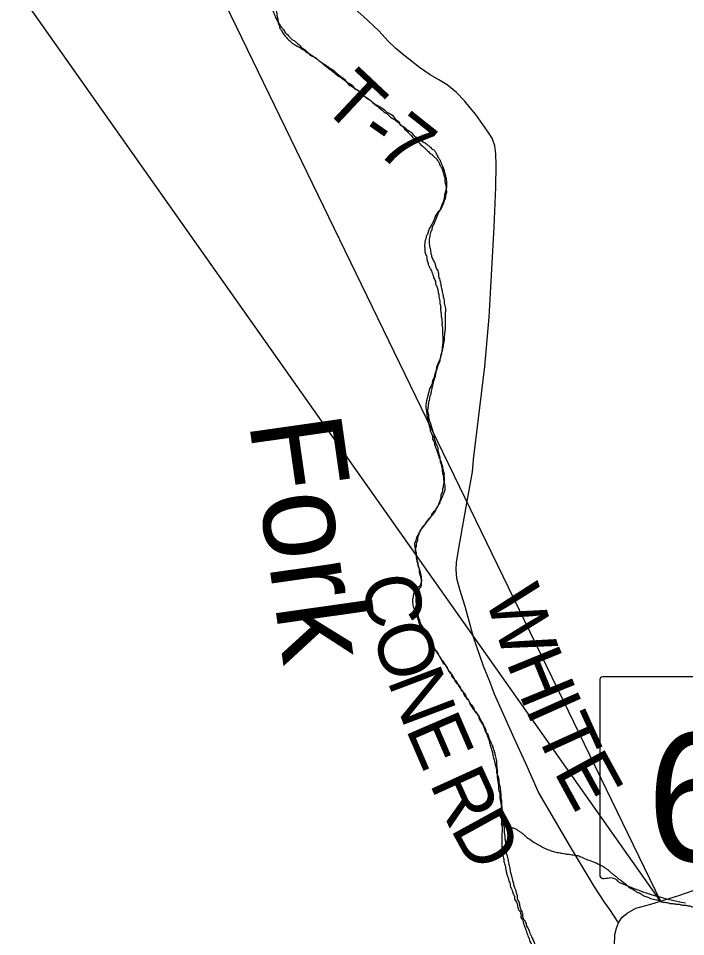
# Model space of a CAD drawing. Extents: x -13.7 to 34, y 0 to 32.3.
# Drawn here: x 26.173 to 26.859, y 17.062 to 18.005 of the extents above; entities that cross this region are included whole.
import ezdxf

# ---------------------------------------------------------------- set-up
doc = ezdxf.new("R2010")
doc.units = 0
for name, color, linetype in [('GM_X_Minor_River', 7, 'Continuous'), ('GM_X_Minor_River_Text', 7, 'Continuous'), ('GM_X_State_Route', 7, 'Continuous'), ('GM_X_State_Shield', 7, 'Continuous'), ('GM_X_Township_Road', 7, 'Continuous'), ('GM_X_Township_Road_Text', 7, 'Continuous'), ('SH_Text', 7, 'Continuous')]:
    doc.layers.add(name, color=color, linetype=linetype)

msp = doc.modelspace()

# ---------------------------------------------------------------- linework, layer by layer
at = {"layer": 'GM_X_Minor_River'}
for points in [[(26.37946, 18.13129), (26.38076, 18.13171), (26.38145, 18.1294), (26.38367, 18.12781), (26.38511, 18.12548), (26.3862, 18.12393), (26.38691, 18.12239), (26.38834, 18.11968), (26.39049, 18.11581), (26.39082, 18.11428), (26.393, 18.11154), (26.39548, 18.10615), (26.39689, 18.10268), (26.39832, 18.09997), (26.39825, 18.09807), (26.40041, 18.09458), (26.40287, 18.08842), (26.40317, 18.08613), (26.40495, 18.08265), (26.40844, 18.07342), (26.41095, 18.06878), (26.41128, 18.06725), (26.41272, 18.06492), (26.41451, 18.06182), (26.41593, 18.05873), (26.41737, 18.0564), (26.4188, 18.0537), (26.42129, 18.04868), (26.42238, 18.04712), (26.42308, 18.04558), (26.42417, 18.04402), (26.42523, 18.04171), (26.42592, 18.0394), (26.42767, 18.03517), (26.42904, 18.03056), (26.42936, 18.02865), (26.43041, 18.02596), (26.43181, 18.02249), (26.43176, 18.02097), (26.43247, 18.01943), (26.43351, 18.01636), (26.4349, 18.01251), (26.43595, 18.00982), (26.437, 18.00712), (26.43806, 18.00481), (26.43913, 18.00287), (26.43984, 18.00133), (26.44052, 17.99903), (26.44123, 17.99748), (26.44156, 17.99595), (26.44227, 17.99441), (26.44336, 17.99285), (26.44588, 17.98897), (26.4488, 17.98545), (26.45064, 17.98349), (26.45248, 17.98191), (26.45395, 17.98034), (26.45581, 17.97914), (26.45767, 17.97794), (26.46214, 17.97551), (26.46437, 17.97392), (26.4666, 17.97271), (26.46882, 17.97073), (26.47031, 17.96992), (26.4796, 17.96392), (26.4885, 17.95754), (26.49036, 17.95634), (26.4922, 17.95476), (26.49444, 17.95355), (26.50036, 17.94879), (26.5022, 17.94721), (26.50554, 17.94482), (26.50886, 17.94205), (26.51181, 17.93929), (26.51737, 17.93531), (26.51808, 17.93376), (26.52365, 17.93016), (26.52434, 17.92786), (26.52694, 17.92625), (26.53326, 17.92224), (26.53549, 17.92065), (26.5377, 17.91868), (26.53918, 17.91749), (26.54141, 17.91627), (26.54922, 17.91146), (26.55217, 17.9087), (26.55591, 17.90706), (26.56141, 17.90117), (26.56472, 17.89802), (26.56505, 17.89649), (26.56765, 17.89451), (26.5702, 17.89138), (26.57204, 17.8898), (26.57498, 17.88667), (26.5816, 17.88037), (26.58345, 17.87879), (26.58603, 17.87642)], [(26.43245, 18.03045), (26.43384, 18.02661), (26.43491, 18.02429), (26.43524, 18.02276), (26.43594, 18.02121), (26.43765, 18.01546), (26.43795, 18.01317), (26.43861, 18.01011), (26.43889, 18.00706), (26.43957, 18.00476), (26.43988, 18.00247), (26.44093, 17.99977), (26.44201, 17.99822), (26.4431, 17.99666), (26.44601, 17.99277), (26.44708, 17.99083), (26.44856, 17.98964), (26.4526, 17.98533), (26.45481, 17.98335), (26.4563, 17.98254), (26.45926, 17.98017), (26.4611, 17.97859), (26.46258, 17.9774), (26.46367, 17.97584), (26.46515, 17.97465), (26.46997, 17.97107), (26.47327, 17.96754), (26.47476, 17.96674), (26.47737, 17.96551), (26.48625, 17.95838), (26.48995, 17.95559), (26.49439, 17.95203), (26.49846, 17.94885), (26.50402, 17.94487), (26.50588, 17.94367), (26.50772, 17.94209), (26.5092, 17.9409), (26.51068, 17.93971), (26.51362, 17.93657), (26.51549, 17.93575), (26.51883, 17.93336), (26.52032, 17.93255), (26.52254, 17.93096), (26.5255, 17.92858), (26.53288, 17.92226), (26.53437, 17.92145), (26.53695, 17.91908), (26.54028, 17.91631), (26.54361, 17.91392), (26.55026, 17.90838), (26.55175, 17.90757), (26.55395, 17.90522), (26.55729, 17.90283), (26.56026, 17.90083), (26.56174, 17.89964), (26.56397, 17.89805), (26.5684, 17.89448), (26.5699, 17.89367), (26.57136, 17.89211), (26.57395, 17.89012), (26.57581, 17.88892), (26.57729, 17.88773), (26.57874, 17.88578), (26.58208, 17.88339), (26.58358, 17.88296), (26.58543, 17.88138), (26.5869, 17.87981), (26.58914, 17.8786), (26.59099, 17.8774), (26.59322, 17.8758), (26.59543, 17.87383), (26.59691, 17.87264), (26.59838, 17.87107), (26.59987, 17.87026), (26.60205, 17.86753), (26.60347, 17.86444), (26.60455, 17.86251), (26.60635, 17.85979), (26.6074, 17.85709), (26.60845, 17.8544), (26.60916, 17.85286), (26.60986, 17.85093), (26.61056, 17.84939), (26.61088, 17.84748), (26.61155, 17.8448), (26.61256, 17.84097), (26.61284, 17.83792), (26.61313, 17.83525), (26.61304, 17.83259), (26.61259, 17.83033), (26.61171, 17.82656), (26.61085, 17.82354), (26.61077, 17.82127), (26.61034, 17.81976), (26.60991, 17.81825), (26.60825, 17.81375), (26.60698, 17.80999)], [(26.58603, 17.87642), (26.58749, 17.87485), (26.59118, 17.87169), (26.59265, 17.87012), (26.5945, 17.86854), (26.59596, 17.86697), (26.59782, 17.86577), (26.60002, 17.86342), (26.6026, 17.86105), (26.60369, 17.8595), (26.60551, 17.85716), (26.60619, 17.85486), (26.60799, 17.85176), (26.60937, 17.84791), (26.6104, 17.84446), (26.61139, 17.83986), (26.61131, 17.83759), (26.61233, 17.83413), (26.6126, 17.83071), (26.6129, 17.82804), (26.61284, 17.82652), (26.6124, 17.82463), (26.61192, 17.82161), (26.61148, 17.81972), (26.61067, 17.81823), (26.61024, 17.81672), (26.60942, 17.81485), (26.60859, 17.8126), (26.60696, 17.80923), (26.6042, 17.80629), (26.60016, 17.79882), (26.59892, 17.79582), (26.59569, 17.78985), (26.59403, 17.78573), (26.59359, 17.78384), (26.5924, 17.78236), (26.59195, 17.78009), (26.59109, 17.77708), (26.59061, 17.77406), (26.59051, 17.77102), (26.59076, 17.76722), (26.59071, 17.7657), (26.59139, 17.7634), (26.59277, 17.75917), (26.59272, 17.75765), (26.59342, 17.75573), (26.5941, 17.75343), (26.59514, 17.75035), (26.59585, 17.74881), (26.59693, 17.74725), (26.59798, 17.74456), (26.59903, 17.74186), (26.60006, 17.73841), (26.60183, 17.73455), (26.60178, 17.73303), (26.60284, 17.73072), (26.60386, 17.72727), (26.60485, 17.72267), (26.60517, 17.72076), (26.60546, 17.71809), (26.60613, 17.71541), (26.60608, 17.71389), (26.60673, 17.71083), (26.60699, 17.70702), (26.60694, 17.70551), (26.60726, 17.7036), (26.60751, 17.69979), (26.60784, 17.69826), (26.60815, 17.69635), (26.60841, 17.69254), (26.60836, 17.69102), (26.60867, 17.68911), (26.60894, 17.68568), (26.60883, 17.68227), (26.60909, 17.67884), (26.6087, 17.66707), (26.6082, 17.66329), (26.60772, 17.66027), (26.60729, 17.65876), (26.60644, 17.65613), (26.60598, 17.65348), (26.60553, 17.6516), (26.60472, 17.65011), (26.60388, 17.64747), (26.60221, 17.64297), (26.60177, 17.64108), (26.60083, 17.63579), (26.60001, 17.63392), (26.59917, 17.63129), (26.59869, 17.62827), (26.59783, 17.62526), (26.59736, 17.62261), (26.59648, 17.61884), (26.59562, 17.61583), (26.59515, 17.61318), (26.59424, 17.60866), (26.59417, 17.60638)], [(26.60698, 17.80999), (26.60535, 17.80663), (26.60373, 17.80364), (26.60247, 17.79988), (26.60125, 17.79726), (26.60041, 17.79501), (26.5992, 17.79277), (26.59838, 17.7909), (26.59751, 17.78751), (26.59668, 17.78564), (26.59626, 17.78413), (26.59579, 17.78149), (26.59531, 17.77846), (26.59522, 17.77581), (26.5955, 17.77276), (26.59579, 17.77009), (26.59647, 17.76779), (26.59675, 17.76474), (26.59742, 17.76206), (26.59881, 17.75821), (26.59988, 17.7559), (26.60095, 17.75396), (26.60161, 17.7509), (26.60338, 17.74704), (26.60475, 17.74243), (26.60467, 17.74016), (26.60573, 17.73784), (26.60639, 17.73478), (26.60707, 17.73248), (26.60738, 17.73019), (26.60838, 17.72598), (26.6087, 17.72445), (26.60937, 17.72176), (26.60968, 17.71947), (26.61036, 17.71717), (26.61067, 17.71488), (26.61093, 17.71145), (26.6116, 17.70877), (26.61189, 17.7061), (26.61179, 17.70307), (26.61172, 17.70079), (26.61109, 17.68181), (26.61061, 17.67879), (26.61047, 17.67461), (26.60999, 17.67159), (26.60952, 17.66895), (26.60904, 17.66592), (26.60818, 17.66291), (26.60733, 17.6599), (26.60644, 17.65613), (26.60601, 17.65462), (26.60226, 17.64449), (26.60221, 17.64297), (26.60139, 17.6411), (26.60052, 17.63771), (26.60009, 17.6362), (26.59845, 17.63245), (26.5984, 17.63094), (26.59675, 17.62719), (26.59423, 17.61968), (26.59334, 17.6159), (26.59291, 17.6144), (26.59247, 17.61251), (26.59217, 17.60341), (26.5925, 17.60187), (26.59273, 17.59731), (26.5934, 17.59463), (26.59406, 17.59156), (26.5947, 17.58812), (26.59607, 17.58352), (26.59638, 17.58161), (26.59743, 17.57891), (26.59882, 17.57507), (26.59876, 17.57317), (26.59983, 17.57123), (26.60051, 17.56855), (26.60153, 17.5651), (26.60258, 17.5624), (26.60397, 17.55856), (26.60464, 17.55588), (26.60712, 17.55047), (26.60779, 17.54779), (26.60884, 17.5451), (26.60879, 17.54358), (26.60947, 17.54128), (26.6098, 17.53975), (26.61051, 17.5382), (26.61043, 17.53593), (26.61071, 17.53288), (26.61061, 17.52984), (26.6109, 17.52717), (26.61063, 17.51882), (26.60982, 17.51733), (26.60855, 17.51357), (26.6061, 17.50833), (26.60567, 17.50683), (26.60449, 17.50535)], [(26.59417, 17.60638), (26.59371, 17.60411), (26.59364, 17.60184), (26.59394, 17.59955), (26.59464, 17.59762), (26.59458, 17.59611), (26.59663, 17.5892), (26.59696, 17.58767), (26.59765, 17.58537), (26.59868, 17.58229), (26.59935, 17.57961), (26.60004, 17.57731), (26.59999, 17.57579), (26.60169, 17.57003), (26.60202, 17.5685), (26.6031, 17.56657), (26.60441, 17.56044), (26.60544, 17.55699), (26.60611, 17.55431), (26.60639, 17.55126), (26.60704, 17.5482), (26.60839, 17.54283), (26.60868, 17.54016), (26.60932, 17.53672), (26.61001, 17.53442), (26.60995, 17.5329), (26.61026, 17.53061), (26.61018, 17.52834), (26.6097, 17.52531), (26.60924, 17.52267), (26.60881, 17.52116), (26.60876, 17.51964), (26.60792, 17.51739), (26.60705, 17.514), (26.607, 17.51248), (26.60615, 17.50985), (26.60489, 17.50609), (26.60408, 17.5046), (26.60327, 17.50311), (26.60205, 17.50049), (26.59411, 17.49011), (26.59251, 17.4875), (26.59052, 17.48491), (26.58934, 17.48343), (26.58736, 17.48122), (26.58416, 17.476), (26.58332, 17.47375), (26.58212, 17.47189), (26.58165, 17.46925), (26.58044, 17.46701), (26.58032, 17.46321), (26.5813, 17.45862), (26.58191, 17.45404), (26.58249, 17.4487), (26.5832, 17.44716), (26.58349, 17.44449), (26.58486, 17.43988), (26.58555, 17.43796), (26.58622, 17.43528), (26.58714, 17.42841), (26.58706, 17.42613), (26.58623, 17.42388), (26.5854, 17.422), (26.58347, 17.42093), (26.58192, 17.41984), (26.58111, 17.41835), (26.58027, 17.4161), (26.57909, 17.41462), (26.57904, 17.4131), (26.57861, 17.41159), (26.57856, 17.41007), (26.57813, 17.40857), (26.57805, 17.40629), (26.57834, 17.40362), (26.57865, 17.40133), (26.57934, 17.39941), (26.58076, 17.39632), (26.58146, 17.3944), (26.5814, 17.39288), (26.58247, 17.39057), (26.58421, 17.38595), (26.5849, 17.38365), (26.58706, 17.38015), (26.58993, 17.37512), (26.59024, 17.37321), (26.59244, 17.37086), (26.59424, 17.36776), (26.59533, 17.3662), (26.59677, 17.36387), (26.59784, 17.36194), (26.60001, 17.35845), (26.60218, 17.35534), (26.60399, 17.35262), (26.60543, 17.35029), (26.60652, 17.34873), (26.60867, 17.34486), (26.60937, 17.34332)], [(26.60449, 17.50535), (26.60248, 17.50199), (26.6005, 17.4994), (26.59772, 17.49569), (26.59648, 17.49269), (26.59334, 17.48976), (26.59135, 17.48678), (26.59054, 17.48529), (26.58858, 17.48346), (26.58697, 17.48085), (26.58534, 17.47748), (26.58411, 17.47448), (26.58325, 17.47147), (26.58318, 17.46957), (26.58276, 17.46807), (26.58191, 17.46544), (26.58186, 17.46392), (26.58097, 17.46015), (26.58123, 17.45634), (26.58254, 17.45022), (26.58281, 17.44679), (26.58385, 17.44372), (26.58418, 17.44218), (26.58486, 17.43988), (26.58481, 17.43836), (26.58544, 17.43454), (26.58647, 17.43109), (26.58711, 17.42765), (26.58704, 17.42537), (26.58612, 17.42084), (26.58453, 17.41861), (26.5837, 17.41636), (26.58289, 17.41487), (26.58207, 17.413), (26.58153, 17.40808), (26.58148, 17.40656), (26.58181, 17.40503), (26.58173, 17.40275), (26.58264, 17.39588), (26.58334, 17.39396), (26.58434, 17.38975), (26.58505, 17.3882), (26.58537, 17.38667), (26.58641, 17.3836), (26.58856, 17.37972), (26.5907, 17.37547), (26.59359, 17.3712), (26.59468, 17.36964), (26.59645, 17.36579), (26.59754, 17.36423), (26.59895, 17.36114), (26.60147, 17.35688), (26.60437, 17.35261), (26.60508, 17.35106), (26.60724, 17.34757), (26.6098, 17.34482), (26.61086, 17.34251), (26.61231, 17.34018), (26.61338, 17.33825), (26.61556, 17.33514), (26.61807, 17.33087), (26.6184, 17.32934), (26.62097, 17.3266), (26.62387, 17.3227), (26.62602, 17.31883), (26.62821, 17.3161), (26.63037, 17.31261), (26.6307, 17.31107), (26.63289, 17.30834), (26.63615, 17.30368), (26.63685, 17.30175), (26.63936, 17.29749), (26.64082, 17.29554), (26.64374, 17.29202), (26.647, 17.28736), (26.64841, 17.28427), (26.65021, 17.28117), (26.65161, 17.2777), (26.6534, 17.27422), (26.65335, 17.27271), (26.6548, 17.27076), (26.65656, 17.26652), (26.65796, 17.26305), (26.66008, 17.25843), (26.66078, 17.2565), (26.66146, 17.2542), (26.66216, 17.25228), (26.66282, 17.24922), (26.6635, 17.24691), (26.66417, 17.24423), (26.66445, 17.24118), (26.6644, 17.23966), (26.66468, 17.23661), (26.66526, 17.23127), (26.66519, 17.229), (26.6654, 17.22405), (26.66573, 17.22252)], [(26.60937, 17.34332), (26.61195, 17.34095), (26.61482, 17.33592), (26.61553, 17.33437), (26.61773, 17.33202), (26.62026, 17.32814), (26.62203, 17.32428), (26.62496, 17.32115), (26.62749, 17.31726), (26.62818, 17.31534), (26.63038, 17.31298), (26.63291, 17.3091), (26.63324, 17.30757), (26.63508, 17.30561), (26.63687, 17.30251), (26.63906, 17.29978), (26.64157, 17.29551), (26.6419, 17.29398), (26.64372, 17.29165), (26.64624, 17.28738), (26.64657, 17.28585), (26.64945, 17.28119), (26.65087, 17.27811), (26.65156, 17.27618), (26.65261, 17.27349), (26.6544, 17.27001), (26.65543, 17.26694), (26.65648, 17.26424), (26.65715, 17.26156), (26.65748, 17.26003), (26.65816, 17.25773), (26.65954, 17.2535), (26.66022, 17.2512), (26.66054, 17.24929), (26.66153, 17.2447), (26.66223, 17.24277), (26.66287, 17.23933), (26.6639, 17.23588), (26.66454, 17.23244), (26.66449, 17.23092), (26.66554, 17.22823), (26.66683, 17.22134), (26.66714, 17.21905), (26.66782, 17.21675), (26.66811, 17.21408), (26.66843, 17.21217), (26.66871, 17.20912), (26.66898, 17.20607), (26.66893, 17.20456), (26.66926, 17.20303), (26.66957, 17.20074), (26.66948, 17.19808), (26.66978, 17.19579), (26.66936, 17.18288), (26.66965, 17.18021), (26.66957, 17.17794), (26.66989, 17.17603), (26.67019, 17.17374), (26.66975, 17.16045), (26.67002, 17.15703), (26.66992, 17.15399), (26.67022, 17.1517), (26.6708, 17.14636), (26.67111, 17.14407), (26.67179, 17.14177), (26.67209, 17.13948), (26.67276, 17.1368), (26.67408, 17.13067), (26.67472, 17.12723), (26.67576, 17.12416), (26.67647, 17.12261), (26.67711, 17.11917), (26.67852, 17.11571), (26.67847, 17.11419), (26.67953, 17.11187), (26.68058, 17.10918), (26.68162, 17.1061), (26.68302, 17.10264), (26.68296, 17.10074), (26.6844, 17.09841), (26.6858, 17.09494), (26.68612, 17.09304), (26.68645, 17.0915), (26.68788, 17.0888), (26.68961, 17.0838), (26.68955, 17.0819), (26.69099, 17.07957), (26.69201, 17.07612), (26.69234, 17.07459), (26.69305, 17.07305), (26.6941, 17.07035), (26.69618, 17.0642), (26.69722, 17.06151), (26.69793, 17.05997), (26.6986, 17.05729), (26.70004, 17.05496), (26.70111, 17.05264)], [(26.66573, 17.22252), (26.66635, 17.21832), (26.66658, 17.21375), (26.6679, 17.20763), (26.66783, 17.20573), (26.66845, 17.20153), (26.66878, 17.2), (26.6694, 17.1958), (26.66973, 17.19427), (26.67035, 17.19007), (26.67029, 17.18817), (26.67057, 17.18512), (26.67118, 17.18054), (26.67112, 17.17902), (26.67179, 17.17634), (26.67243, 17.17252), (26.67232, 17.16911), (26.67293, 17.1649), (26.67289, 17.16339), (26.67353, 17.15995), (26.67344, 17.15729), (26.67443, 17.1527), (26.67462, 17.14699), (26.67532, 17.14507), (26.67597, 17.14201), (26.67695, 17.13704), (26.67726, 17.13513), (26.67793, 17.13244), (26.67858, 17.129), (26.6806, 17.12134), (26.68093, 17.11981), (26.68193, 17.11559), (26.68226, 17.11406), (26.68332, 17.11175), (26.68436, 17.10867), (26.68503, 17.10599), (26.68569, 17.10293), (26.68564, 17.10141), (26.6867, 17.09909), (26.68807, 17.09449), (26.68838, 17.09258), (26.68979, 17.08911), (26.69114, 17.08413), (26.69144, 17.08184), (26.69324, 17.07874), (26.695, 17.0745), (26.69533, 17.07297), (26.69677, 17.07064), (26.69817, 17.06718), (26.69922, 17.06448), (26.70064, 17.0614), (26.70171, 17.05946), (26.70241, 17.05754), (26.70347, 17.05522), (26.70414, 17.05254), (26.70593, 17.04944), (26.70698, 17.04675), (26.70951, 17.04286), (26.71089, 17.03864), (26.71417, 17.03435), (26.71594, 17.03049), (26.71883, 17.02622), (26.7206, 17.02236), (26.7224, 17.01926), (26.72418, 17.01578), (26.72413, 17.01426), (26.72594, 17.01154), (26.7277, 17.0073), (26.72765, 17.00578), (26.7291, 17.00384), (26.73052, 17.00075), (26.73155, 16.99768), (26.73297, 16.99459), (26.73292, 16.99307), (26.73399, 16.99113), (26.73502, 16.98768), (26.73566, 16.98424), (26.73668, 16.98041), (26.73803, 16.97542), (26.73798, 16.9739), (26.7386, 16.9697), (26.73924, 16.96626), (26.73954, 16.96359), (26.73938, 16.95904), (26.73893, 16.95677), (26.73885, 16.9545), (26.7384, 16.95223), (26.73815, 16.94464), (26.73769, 16.94238), (26.73725, 16.94049), (26.73696, 16.93176), (26.73725, 16.92909), (26.73787, 16.92489), (26.73922, 16.91953), (26.73953, 16.91762), (26.7402, 16.91493), (26.74126, 16.91262)], [(26.67114, 17.17897), (26.66917, 17.17719), (26.67143, 17.17673), (26.67368, 17.1759), (26.67594, 17.17545), (26.67819, 17.17461), (26.68158, 17.17374), (26.68383, 17.1729), (26.68643, 17.1713), (26.6894, 17.1693), (26.692, 17.16732), (26.69458, 17.16495), (26.69902, 17.16176), (26.7046, 17.15816), (26.70684, 17.15694), (26.70944, 17.15534), (26.71168, 17.15413), (26.71691, 17.15167), (26.71916, 17.15084), (26.72179, 17.14999), (26.72404, 17.14916), (26.72668, 17.14869), (26.7297, 17.14821), (26.73197, 17.14775), (26.73499, 17.14727), (26.73914, 17.14675), (26.74443, 17.14582), (26.74783, 17.14533), (26.75195, 17.14367), (26.75794, 17.14119), (26.76469, 17.13869), (26.77254, 17.13501), (26.77478, 17.13379), (26.77737, 17.13181), (26.77959, 17.13022), (26.78217, 17.12785), (26.78513, 17.12547), (26.78772, 17.12349), (26.79216, 17.11992), (26.7955, 17.11753), (26.79771, 17.11556), (26.80103, 17.11278), (26.80587, 17.10996), (26.80847, 17.10798), (26.81184, 17.10673), (26.81481, 17.10473), (26.81893, 17.10307), (26.82268, 17.10143), (26.8287, 17.10009), (26.83171, 17.09923), (26.83395, 17.09801), (26.83999, 17.09705), (26.84338, 17.09618), (26.84565, 17.09611), (26.84905, 17.09561), (26.85133, 17.09554), (26.85472, 17.09467), (26.85737, 17.09458), (26.85963, 17.09412), (26.86303, 17.09363), (26.86566, 17.09278), (26.8687, 17.09268), (26.87247, 17.09218), (26.87892, 17.09196), (26.88118, 17.09151), (26.8846, 17.0914), (26.88689, 17.0917), (26.88994, 17.09236), (26.89344, 17.0949), (26.89807, 17.09703), (26.90083, 17.09998), (26.90587, 17.10323), (26.91058, 17.10801), (26.91334, 17.11096), (26.91502, 17.11585), (26.92376, 17.12772), (26.92461, 17.13035), (26.92812, 17.13327), (26.93096, 17.13888), (26.93373, 17.14221), (26.93532, 17.14443), (26.93656, 17.14743), (26.94017, 17.15339), (26.9418, 17.15676), (26.94227, 17.1594), (26.94552, 17.16575), (26.94597, 17.16802), (26.94797, 17.17099), (26.94966, 17.17625), (26.95127, 17.17886), (26.95253, 17.18262), (26.95454, 17.18597), (26.95581, 17.19011), (26.95787, 17.19498), (26.96187, 17.20093), (26.96548, 17.20689), (26.96749, 17.21024)]]:
    msp.add_spline(points, degree=3, dxfattribs=at)
at = {"layer": 'GM_X_State_Route'}
msp.add_lwpolyline([(26.78576, 17.05253), (26.78594, 17.0644), (26.78764, 17.0708), (26.78979, 17.07635), (26.79308, 17.08189), (26.79869, 17.08634), (26.80744, 17.09133), (26.82288, 17.09536), (26.85177, 17.10446), (26.87331, 17.11184)], dxfattribs=at)
at = {"layer": 'GM_X_State_Shield'}
for p, q in [((26.87023, 17.32904), (26.77371, 17.32904)), ((26.77046, 17.3256), (26.77046, 17.12548))]:
    msp.add_line(p, q, dxfattribs=at)
for centre, major_axis, start_param, end_param in [((26.77424, 17.32602), (0.00382, 0), 1.712693, 3.28349), ((26.77427, 17.12504), (0.00385, 0), 3.00124, 4.508301), ((26.77486, 17.14551), (0.0294, 0), 4.665946, 4.897461), ((26.78087, 17.11393), (0.0106, 0), 0.519207, 1.627899), ((26.91469, 17.29373), (0.2524, 0), 4.195997, 4.488961)]:
    msp.add_ellipse(centre, major_axis=major_axis, ratio=0.8, start_param=start_param, end_param=end_param, dxfattribs=at)
at = {"layer": 'GM_X_Township_Road'}
msp.add_lwpolyline([(26.78979, 17.07635), (26.78076, 17.08989), (26.77523, 17.09769), (26.76517, 17.11329), (26.74054, 17.15433), (26.7075, 17.21056), (26.69437, 17.2399), (26.68247, 17.26617), (26.66236, 17.31131), (26.65764, 17.32424), (26.65107, 17.34004), (26.64066, 17.36979), (26.63219, 17.40119), (26.62674, 17.41868), (26.62357, 17.43013), (26.62296, 17.43936), (26.62314, 17.44658), (26.62562, 17.46132), (26.63498, 17.51332), (26.63958, 17.53951), (26.64081, 17.55223), (26.6523, 17.64786), (26.65702, 17.69854), (26.66215, 17.79089), (26.66359, 17.83214), (26.664, 17.85471), (26.66379, 17.86641), (26.66277, 17.87461), (26.65989, 17.88221), (26.65518, 17.88939), (26.64307, 17.90663), (26.63732, 17.9134), (26.63137, 17.92079), (26.62337, 17.92941), (26.61352, 17.9372), (26.60511, 17.94234), (26.59607, 17.94726), (26.5854, 17.95506), (26.56919, 17.96758), (26.56078, 17.97455), (26.55261, 17.98223), (26.54375, 17.9922), (26.53184, 18.00349), (26.51851, 18.01539)], dxfattribs=at)
at = {"layer": 'SH_Text'}
msp.add_lwpolyline([(26.83294, 17.09852), (26.173, 18.03325), (26.173, 18.45829)], close=True, dxfattribs=at)

# ---------------------------------------------------------------- texts
at = {"layer": 'GM_X_Minor_River_Text'}
msp.add_text('Fork', height=0.094706, rotation=278.10108, dxfattribs=at).set_placement((26.4098, 17.59093))
at = {"layer": 'GM_X_State_Shield'}
msp.add_text('689', height=0.131836, dxfattribs=at).set_placement((26.81893, 17.13959))
at = {"layer": 'GM_X_Township_Road_Text'}
for s, rotation, p in [('T', 316.77463, (26.4826, 17.91595)), ('7', 321.50111, (26.53873, 17.86849)), ('-', 324.98965, (26.52035, 17.88133)), ('C', 280.48324, (26.52539, 17.4296)), ('W', 287.54252, (26.65225, 17.4118)), ('O', 287.39183, (26.53568, 17.37646)), ('H', 292.23116, (26.67379, 17.34434)), ('N', 290.68557, (26.55179, 17.32537)), ('I', 294.01527, (26.69345, 17.29631)), ('E', 293.37045, (26.57054, 17.2759)), ('T', 294.38029, (26.70311, 17.27464)), ('E', 298.64423, (26.72268, 17.23187)), ('R', 294.50639, (26.59503, 17.21978)), ('D', 298.74572, (26.61644, 17.17321))]:
    msp.add_text(s, height=0.05682, rotation=rotation, dxfattribs=at).set_placement(p)

doc.saveas('drawing.dxf')
